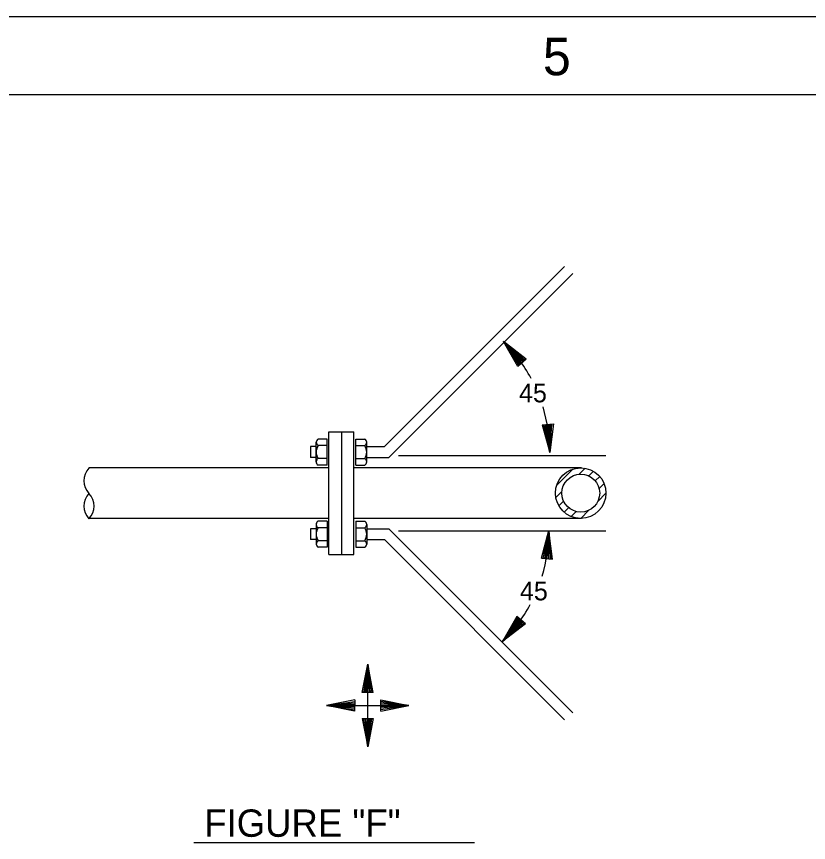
# Model space of a CAD drawing. Extents: x 10040.55 to 10045.84, y 10033.26 to 10035.76.
# Drawn here: x 10041.2595 to 10041.6823, y 10035.3149 to 10035.7555 of the extents above; entities that cross this region are included whole.
import ezdxf

# ---------------------------------------------------------------- set-up
doc = ezdxf.new("R2010")
doc.units = 0
doc.layers.add('Level 1', color=7, linetype='Continuous')
doc.layers.add('Level 2', color=7, linetype='Continuous')

msp = doc.modelspace()

# ---------------------------------------------------------------- linework, layer by layer
at = {"layer": 'Level 1'}
for p, q in [((10040.54696875, 10035.755520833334), (10044.04696875, 10035.755520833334)), ((10040.713635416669, 10035.713854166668), (10044.005302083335, 10035.713854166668))]:
    msp.add_line(p, q, dxfattribs=at)
at = {"layer": 'Level 2'}
for p, q in [((10041.455947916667, 10035.526052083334), (10041.552125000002, 10035.622229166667)), ((10041.458322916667, 10035.520333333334), (10041.556437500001, 10035.618447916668)), ((10041.529427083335, 10035.570791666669), (10041.51946875, 10035.582093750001)), ((10041.527114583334, 10035.568791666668), (10041.51946875, 10035.582093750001)), ((10041.531656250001, 10035.572750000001), (10041.51946875, 10035.582093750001)), ((10041.51946875, 10035.582093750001), (10041.528302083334, 10035.569791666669)), ((10041.51946875, 10035.582093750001), (10041.530458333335, 10035.571677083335)), ((10041.51946875, 10035.582093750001), (10041.527750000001, 10035.569333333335)), ((10041.51946875, 10035.582093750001), (10041.528843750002, 10035.570291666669)), ((10041.51946875, 10035.582093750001), (10041.529947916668, 10035.571260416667)), ((10041.51946875, 10035.582093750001), (10041.531083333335, 10035.572250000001)), ((10041.531656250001, 10035.572750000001), (10041.527114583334, 10035.568791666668)), ((10041.540197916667, 10035.537718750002), (10041.546218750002, 10035.538145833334)), ((10041.540197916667, 10035.537718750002), (10041.54425, 10035.522916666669)), ((10041.54425, 10035.522916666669), (10041.540968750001, 10035.537781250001)), ((10041.54425, 10035.522916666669), (10041.541802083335, 10035.537854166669)), ((10041.54425, 10035.522916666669), (10041.542468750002, 10035.537885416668)), ((10041.543177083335, 10035.537937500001), (10041.54425, 10035.522916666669)), ((10041.54425, 10035.522916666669), (10041.543927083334, 10035.537989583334)), ((10041.546218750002, 10035.538145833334), (10041.54425, 10035.522916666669)), ((10041.54425, 10035.522916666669), (10041.545395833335, 10035.538083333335)), ((10041.54425, 10035.522916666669), (10041.544677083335, 10035.538052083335)), ((10041.425406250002, 10035.530135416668), (10041.420593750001, 10035.530135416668)), ((10041.425406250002, 10035.516218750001), (10041.425406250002, 10035.530135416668)), ((10041.426177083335, 10035.468562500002), (10041.426177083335, 10035.533937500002)), ((10041.426177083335, 10035.533937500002), (10041.43965625, 10035.533937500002)), ((10041.433, 10035.533937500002), (10041.433, 10035.468562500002)), ((10041.43965625, 10035.468562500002), (10041.43965625, 10035.533937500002)), ((10041.440583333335, 10035.516218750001), (10041.440583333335, 10035.530135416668)), ((10041.440583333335, 10035.530135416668), (10041.445385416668, 10035.530135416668)), ((10041.419489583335, 10035.526052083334), (10041.416541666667, 10035.526052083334)), ((10041.416541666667, 10035.526052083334), (10041.416541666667, 10035.520333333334)), ((10041.419500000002, 10035.517979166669), (10041.419500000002, 10035.528395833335)), ((10041.425406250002, 10035.526677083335), (10041.420562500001, 10035.526677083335)), ((10041.440583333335, 10035.526677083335), (10041.445427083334, 10035.526677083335)), ((10041.446489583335, 10035.517979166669), (10041.446489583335, 10035.528395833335)), ((10041.446500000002, 10035.526052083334), (10041.455947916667, 10035.526052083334)), ((10041.463364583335, 10035.521291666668), (10041.574083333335, 10035.521291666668)), ((10041.419489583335, 10035.520333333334), (10041.416541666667, 10035.520333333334)), ((10041.425406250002, 10035.519666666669), (10041.420562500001, 10035.519666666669)), ((10041.440583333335, 10035.519666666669), (10041.445427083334, 10035.519666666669)), ((10041.446500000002, 10035.520333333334), (10041.458322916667, 10035.520333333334)), ((10041.426177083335, 10035.514750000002), (10041.298177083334, 10035.514750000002)), ((10041.425406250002, 10035.516218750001), (10041.420562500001, 10035.516218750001)), ((10041.561156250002, 10035.514750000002), (10041.43965625, 10035.514750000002)), ((10041.440583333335, 10035.516218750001), (10041.445427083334, 10035.516218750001)), ((10041.426177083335, 10035.487750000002), (10041.298177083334, 10035.487750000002)), ((10041.425406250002, 10035.486281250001), (10041.420562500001, 10035.486281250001)), ((10041.425406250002, 10035.486281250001), (10041.425406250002, 10035.472354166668)), ((10041.426177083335, 10035.487750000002), (10041.426177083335, 10035.487750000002)), ((10041.561156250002, 10035.487750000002), (10041.43965625, 10035.487750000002)), ((10041.440583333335, 10035.486281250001), (10041.440583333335, 10035.472354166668)), ((10041.440583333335, 10035.486281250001), (10041.445427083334, 10035.486281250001)), ((10041.419406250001, 10035.482177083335), (10041.416479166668, 10035.482177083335)), ((10041.416479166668, 10035.482177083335), (10041.416479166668, 10035.476458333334)), ((10041.419500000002, 10035.484520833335), (10041.419500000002, 10035.474093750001)), ((10041.425406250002, 10035.482812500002), (10041.420562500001, 10035.482812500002)), ((10041.440583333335, 10035.482812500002), (10041.445427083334, 10035.482812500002)), ((10041.446489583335, 10035.484520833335), (10041.446489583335, 10035.474093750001)), ((10041.446500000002, 10035.482156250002), (10041.458322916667, 10035.482156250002)), ((10041.458322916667, 10035.482156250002), (10041.556437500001, 10035.384052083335)), ((10041.463364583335, 10035.481197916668), (10041.574083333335, 10035.481197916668)), ((10041.539708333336, 10035.466541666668), (10041.543760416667, 10035.481343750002)), ((10041.543760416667, 10035.481343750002), (10041.540479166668, 10035.466479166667)), ((10041.543760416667, 10035.481343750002), (10041.541312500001, 10035.466406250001)), ((10041.543760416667, 10035.481343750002), (10041.541979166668, 10035.466375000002)), ((10041.542687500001, 10035.466322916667), (10041.543760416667, 10035.481343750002)), ((10041.543760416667, 10035.481343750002), (10041.5434375, 10035.466270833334)), ((10041.545729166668, 10035.466114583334), (10041.543760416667, 10035.481343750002)), ((10041.543760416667, 10035.481343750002), (10041.544187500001, 10035.466208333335)), ((10041.543760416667, 10035.481343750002), (10041.544906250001, 10035.466177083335)), ((10041.419406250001, 10035.476458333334), (10041.416479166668, 10035.476458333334)), ((10041.425406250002, 10035.475833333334), (10041.420562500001, 10035.475833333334)), ((10041.425406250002, 10035.472354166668), (10041.420593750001, 10035.472354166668)), ((10041.440583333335, 10035.475833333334), (10041.445427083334, 10035.475833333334)), ((10041.440583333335, 10035.472354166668), (10041.445385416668, 10035.472354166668)), ((10041.446500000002, 10035.476447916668), (10041.455947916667, 10035.476447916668)), ((10041.455947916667, 10035.476447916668), (10041.552125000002, 10035.380270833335)), ((10041.426177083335, 10035.468562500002), (10041.43965625, 10035.468562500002)), ((10041.539708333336, 10035.466541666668), (10041.545729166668, 10035.466114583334)), ((10041.526625, 10035.435468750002), (10041.518979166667, 10035.422166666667)), ((10041.518979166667, 10035.422166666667), (10041.527260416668, 10035.434927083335)), ((10041.518979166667, 10035.422166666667), (10041.5278125, 10035.434468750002)), ((10041.518979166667, 10035.422166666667), (10041.528354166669, 10035.433968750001)), ((10041.528937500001, 10035.433468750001), (10041.518979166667, 10035.422166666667)), ((10041.518979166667, 10035.422166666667), (10041.529458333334, 10035.433)), ((10041.531166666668, 10035.431510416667), (10041.526625, 10035.435468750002)), ((10041.518979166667, 10035.422166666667), (10041.529968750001, 10035.432583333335)), ((10041.518979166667, 10035.422166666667), (10041.530593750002, 10035.432010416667)), ((10041.531166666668, 10035.431510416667), (10041.518979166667, 10035.422166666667)), ((10041.443968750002, 10035.394906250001), (10041.446989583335, 10035.409947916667)), ((10041.446989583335, 10035.409947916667), (10041.444781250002, 10035.394895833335)), ((10041.446989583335, 10035.409947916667), (10041.445510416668, 10035.394885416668)), ((10041.446989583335, 10035.409947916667), (10041.44625, 10035.394895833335)), ((10041.446989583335, 10035.365958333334), (10041.446989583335, 10035.409947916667)), ((10041.447010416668, 10035.394885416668), (10041.446989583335, 10035.409947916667)), ((10041.449989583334, 10035.394895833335), (10041.446989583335, 10035.409947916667)), ((10041.446989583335, 10035.409947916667), (10041.448385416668, 10035.394875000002)), ((10041.446989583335, 10035.409947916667), (10041.447708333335, 10035.394895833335)), ((10041.446989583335, 10035.409947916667), (10041.449229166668, 10035.394895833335)), ((10041.449989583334, 10035.394895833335), (10041.443968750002, 10035.394906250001)), ((10041.440052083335, 10035.390947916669), (10041.425000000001, 10035.387947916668)), ((10041.425000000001, 10035.387947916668), (10041.440052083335, 10035.390187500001)), ((10041.425000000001, 10035.387947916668), (10041.440072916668, 10035.389343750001)), ((10041.425000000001, 10035.387947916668), (10041.440052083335, 10035.388666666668)), ((10041.440052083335, 10035.390947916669), (10041.440041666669, 10035.384927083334)), ((10041.468989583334, 10035.387947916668), (10041.453927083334, 10035.389427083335)), ((10041.4539375, 10035.384947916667), (10041.453947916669, 10035.390968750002)), ((10041.468989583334, 10035.387947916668), (10041.4539375, 10035.390156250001)), ((10041.468989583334, 10035.387947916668), (10041.4539375, 10035.3886875)), ((10041.453947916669, 10035.390968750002), (10041.468989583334, 10035.387947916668)), ((10041.440062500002, 10035.387968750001), (10041.425000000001, 10035.387947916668)), ((10041.425000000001, 10035.387947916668), (10041.468989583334, 10035.387947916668)), ((10041.440041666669, 10035.384927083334), (10041.425000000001, 10035.387947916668)), ((10041.425000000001, 10035.387947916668), (10041.440062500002, 10035.38646875)), ((10041.425000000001, 10035.387947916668), (10041.440052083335, 10035.385739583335)), ((10041.425000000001, 10035.387947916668), (10041.440052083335, 10035.387208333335)), ((10041.468989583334, 10035.387947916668), (10041.453916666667, 10035.386552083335)), ((10041.453927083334, 10035.387927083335), (10041.468989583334, 10035.387947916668)), ((10041.4539375, 10035.384947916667), (10041.468989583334, 10035.387947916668)), ((10041.468989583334, 10035.387947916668), (10041.4539375, 10035.387229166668)), ((10041.468989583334, 10035.387947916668), (10041.4539375, 10035.385708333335)), ((10041.443989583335, 10035.381010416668), (10041.450010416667, 10035.381000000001)), ((10041.443989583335, 10035.381010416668), (10041.446989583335, 10035.365958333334)), ((10041.446989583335, 10035.365958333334), (10041.44475, 10035.381010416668)), ((10041.446989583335, 10035.365958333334), (10041.44559375, 10035.38103125)), ((10041.446989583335, 10035.365958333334), (10041.446270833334, 10035.381010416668)), ((10041.44696875, 10035.381020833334), (10041.446989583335, 10035.365958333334)), ((10041.446989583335, 10035.365958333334), (10041.44846875, 10035.381020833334)), ((10041.446989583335, 10035.365958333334), (10041.449197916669, 10035.381010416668)), ((10041.446989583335, 10035.365958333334), (10041.447729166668, 10035.381010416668)), ((10041.450010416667, 10035.381000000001), (10041.446989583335, 10035.365958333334)), ((10041.354166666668, 10035.314895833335), (10041.504093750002, 10035.314895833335))]:
    msp.add_line(p, q, dxfattribs=at)
for points in [[(10041.547958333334, 10035.50553125), (10041.556489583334, 10035.514041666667)], [(10041.559885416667, 10035.511333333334), (10041.563072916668, 10035.514520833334)], [(10041.565072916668, 10035.510416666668), (10041.567541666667, 10035.512906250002)], [(10041.568520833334, 10035.50775), (10041.570895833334, 10035.510114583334)], [(10041.570572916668, 10035.503697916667), (10041.573218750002, 10035.506343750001)], [(10041.547479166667, 10035.4989375), (10041.550687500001, 10035.502145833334)], [(10041.569864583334, 10035.496864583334), (10041.574208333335, 10035.501218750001)], [(10041.549114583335, 10035.494468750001), (10041.55159375, 10035.496958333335)], [(10041.551875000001, 10035.491125), (10041.55428125, 10035.4935)], [(10041.555687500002, 10035.488802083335), (10041.558333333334, 10035.4914375)], [(10041.560781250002, 10035.487802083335), (10041.565145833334, 10035.492166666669)]]:
    msp.add_lwpolyline(points, dxfattribs=at)
for centre, radius in [((10041.560743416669, 10035.501269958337), 0.013479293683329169), ((10041.56075016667, 10035.501269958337), 0.010123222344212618)]:
    msp.add_circle(centre, radius, dxfattribs=at)
for centre, radius, start, end in [((10041.461195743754, 10035.522921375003), 0.08305132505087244, 28.380758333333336, 45.43875), ((10041.461195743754, 10035.522921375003), 0.08305132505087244, 0, 17.029955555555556), ((10041.42146596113, 10035.528390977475), 0.001946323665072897, 116.78268611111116, 241.83909722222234), ((10041.444519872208, 10035.528390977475), 0.0019463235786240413, 298.1609027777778, 63.217313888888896), ((10041.425936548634, 10035.523170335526), 0.006430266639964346, 147.00615833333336, 212.94297500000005), ((10041.440049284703, 10035.523170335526), 0.006430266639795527, 327.057025, 32.9938416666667), ((10041.421451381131, 10035.517951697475), 0.001946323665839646, 117.88770000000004, 242.03418611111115), ((10041.444534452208, 10035.517951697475), 0.0019463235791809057, 297.9658138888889, 62.112300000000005), ((10041.305170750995, 10035.507836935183), 0.009719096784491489, 135.97880833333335, 224.0225027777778), ((10041.305170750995, 10035.494328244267), 0.009719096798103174, 135.97749722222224, 224.02119166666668), ((10041.291193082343, 10035.494328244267), 0.009719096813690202, 315.97880833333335, 44.02250277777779), ((10041.421451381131, 10035.484547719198), 0.0019463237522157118, 117.9658138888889, 242.1123), ((10041.444534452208, 10035.484547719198), 0.0019463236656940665, 297.8877, 62.03418611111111), ((10041.425936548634, 10035.479329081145), 0.006430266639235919, 147.057025, 212.9938416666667), ((10041.440049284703, 10035.479329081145), 0.006430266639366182, 327.00615833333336, 32.942975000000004), ((10041.46070616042, 10035.48133904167), 0.08305132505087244, 342.97004444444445, 0), ((10041.42146596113, 10035.474108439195), 0.0019463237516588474, 118.16090277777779, 243.2173138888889), ((10041.444519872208, 10035.474108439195), 0.0019463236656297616, 296.78268611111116, 61.83909722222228), ((10041.46070616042, 10035.48133904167), 0.08305132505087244, 314.56125000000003, 331.6192416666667)]:
    msp.add_arc(centre, radius, start, end, dxfattribs=at)

# ---------------------------------------------------------------- texts
at = {"layer": 'Level 1'}
msp.add_text('5', height=0.020000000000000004, dxfattribs=at).set_placement((10041.540552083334, 10035.724187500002))
at = {"layer": 'Level 2'}
for s, height, p in [('45', 0.010000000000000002, (10041.527791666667, 10035.549708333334)), ('45', 0.010000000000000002, (10041.528291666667, 10035.444072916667)), ('FIGURE "F"', 0.014583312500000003, (10041.359739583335, 10035.317927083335))]:
    msp.add_text(s, height=height, dxfattribs=at).set_placement(p)

doc.saveas('drawing.dxf')
